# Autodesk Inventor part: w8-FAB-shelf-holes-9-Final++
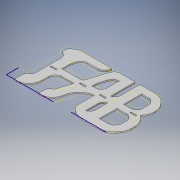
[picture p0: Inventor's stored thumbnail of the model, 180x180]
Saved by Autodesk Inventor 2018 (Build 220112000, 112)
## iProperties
Created: 2018-03
Part Number: w8-FAB-shelf-holes-9-Final++
Material: Generic
Document SubType Name: Modeling
Designer: katin
Density: 1 g/cm^3
Appearance: Default
Mass: 2764.59 g
Surface Area: 5789.53 cm^2
Volume: 2764.59 cm^3
Author: katin
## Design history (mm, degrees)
sketch "Sketch1"
  geometry: L1 (0, -103.188)-(-76.2, -103.188); L2 (-382.588, -407.987)-(-201.613, -407.987); L3 (-201.613, -407.987)-(-179.387, -330.2); L4 (-179.387, -330.2)-(-179.387, -303.315); L5 (-179.387, -303.315)-(-382.588, -303.315); L6 (-382.588, -303.315)-(-382.588, -330.2); L7 (-382.588, -330.2)-(-404.813, -407.987); L8 (-404.813, -407.987)-(-446.104, -500); L9 (-914.4, -410.18)-(-914.4, -330.2); L10 (-914.4, -330.2)-(-863.6, -279.4); L11 (-863.6, -279.4)-(-941.188, -201.812); L12 (-941.188, -100.013)-(-863.6, 0); L13 (-611.188, -500)-(-611.188, -274.637); L14 (-660.987, -274.638)-(-660.987, -501.799); L15 (-660.987, -203.2)-(-660.987, -104.775); L16 (-611.188, -104.775)-(-660.987, -104.775); L17 (-458.721, -302.879)-(-458.721, -330.2); L18 (-458.721, -330.2)-(-480.946, -407.987); L19 (-480.946, -407.987)-(-534.987, -407.987); L20 (-534.987, -407.987)-(-534.988, -302.879); L21 (-534.988, -302.879)-(-458.721, -302.879); L22 (-180.346, -201.117)-(-180.346, -104.775); L23 (-180.346, -104.775)-(-330, -104.775); L24 (-180.346, -201.117)-(-380.371, -201.117); L25 (-380.371, -201.117)-(-330, -104.775); L26 (-458.721, -201.117)-(-458.721, -104.775); L27 (-458.721, -201.117)-(-534.987, -201.117); L28 (-534.987, -201.117)-(-534.987, -104.775); L29 (-739.719, -407.987)-(-739.719, -306.388); L30 (-739.719, -407.987)-(-815.975, -407.987); L31 (-841.375, -354.012)-(-841.375, -381); L32 (-841.375, -381)-(-815.975, -407.987); L33 (-382.588, -407.987)-(-424.795, -502.08); L34 (-79.965, -502.08)-(-424.795, -502.08); L35 (-611.188, -104.775)-(-611.188, -203.2); L36 (-611.188, -500)-(-446.104, -500); L37 (0, -103.188)-(0, 0); L38 (-941.188, -201.812)-(-941.188, -100.013); L39 (0, -103.188)-(0, 0); L40 (0, 0)-(-406.4, 0); L41 (-406.4, 0)-(-458.721, -104.775); L42 (-534.987, -104.775)-(-558.8, 0); L43 (-611.188, -203.2)-(-660.987, -233.363); L44 (-660.987, -233.363)-(-660.987, -203.2); L45 (-558.8, 0)-(-863.6, 0); L46 (0, 0)-(-406.4, 0); L47 (-79.965, -502.08)-(-50.58, -485.849); L48 (-50.58, -485.849)-(-50.58, -407.987); L49 (-50.58, -407.987)-(-76.2, -407.987); L50 (-76.2, -407.987)-(-76.2, -103.188); L51 (-841.375, -354.012)-(-793.75, -306.388); L52 (-793.75, -306.388)-(-739.719, -306.388); L53 (-611.188, -274.637)-(-660.987, -274.638); L54 (-739.762, -201.612)-(-739.762, -103.187); L55 (-739.762, -103.187)-(-836.612, -103.188); L56 (-836.612, -103.188)-(-863.6, -138.112); L57 (-863.6, -138.112)-(-863.6, -176.213); L58 (-863.6, -176.213)-(-838.2, -201.612); L59 (-838.2, -201.612)-(-739.762, -201.612); L60 (-914.4, -410.18)-(-838.2, -501.799); L61 (-838.2, -501.799)-(-660.987, -501.799); L62 (0, 0)-(-406.4, 0); L63 (-558.8, 0)-(-863.6, 0)
  constraints: 126 end point, 13 perpendicular, 13 point on line, 10 vertical, 9 horizontal, 3 collinear, 1 parallel
sketch "Sketch2"
  geometry: L1 (0, 0)-(-940, 0); L2 (-940, 0)-(-940, -500); L3 (-940, -500)-(0, -500); L4 (0, -500)-(0, 0)
  constraints: 8 end point, 2 parallel, 1 horizontal, 1 perpendicular
  dimensions: "d10" = 940 distance of L3.end L2.end; "d11" = 500 distance of L2.end L1.end
extrude "Extrusion2" new body sketch "Sketch2" distance "d12" = 11; taper "d13" = 0 deg
sketch "Sketch3"
  geometry: L1 (0, 0)-(0, 500) reference; L2 (0, 408.758)-(113.674, 408.758); L3 (113.674, 408.758)-(113.674, 94.825); L4 (113.674, 94.825)-(0, 94.825); L5 (0, 94.825)-(0, 408.758); L6 (611.188, 500.062)-(650.182, 500.062); L7 (650.182, 500.062)-(650.182, 287.702); L8 (650.182, 287.702)-(611.188, 287.702); L9 (611.188, 287.702)-(611.188, 500.062); L10 (0, 500)-(129.919, 500); L11 (0, 500)-(940, 500) reference; L12 (129.919, 500)-(0, 408.758); L13 (0, 500)-(0, 408.758); L14 (739.775, 406.4)-(739.775, 307.975); L15 (739.775, 307.975)-(793.75, 307.975); L16 (793.75, 307.975)-(836.612, 350.838); L17 (836.612, 350.838)-(841.375, 355.6); L18 (841.375, 355.6)-(841.375, 381); L19 (841.375, 381)-(806.218, 418.355); L20 (806.218, 418.355)-(739.775, 418.355); L21 (739.775, 418.355)-(739.775, 406.4)
  constraints: 38 end point, 6 parallel, 4 perpendicular, 4 point on line, 2 horizontal, 1 collinear, 1 vertical
extrude "Extrusion3" cut sketch "Sketch3" distance "d14" = 150; taper "d15" = 0 deg
sketch "Sketch4"
  geometry: L1 (0, 500)-(940, 500) reference; L2 (839.788, 500)-(914.4, 411.163); L3 (914.4, 411.163)-(914.4, 310.193); L4 (914.4, 310.193)-(880.473, 275.82); L5 (880.473, 275.82)-(940, 217.064); L6 (940, 217.064)-(940, 500); L7 (940, 500)-(839.788, 500); L8 (940, 0)-(940, 500) reference; L9 (940, 99.14)-(940, 0); L10 (940, 0)-(863.6, 0); L11 (0, 0)-(940, 0) reference; L12 (940, 99.14)-(863.6, 0); L13 (728.744, 226.212)-(728.744, 72.721); L14 (728.744, 72.721)-(830.691, 72.721); L15 (830.691, 72.721)-(864.394, 116.456); L16 (864.394, 116.456)-(864.405, 192.017); L17 (864.405, 192.017)-(829.761, 226.212); L18 (829.761, 226.212)-(728.744, 226.212); L19 (649.575, 72.721)-(649.575, 226.081); L20 (649.575, 226.081)-(611.188, 202.869); L21 (611.188, 202.869)-(611.188, 72.721); L22 (611.188, 72.721)-(649.575, 72.721); L23 (727.378, 439.44)-(727.378, 283.141); L24 (727.378, 283.141)-(801.955, 283.141); L25 (801.955, 283.141)-(841.375, 322.561); L26 (841.375, 322.561)-(841.375, 403.65); L27 (841.375, 403.65)-(807.69, 439.44); L28 (807.69, 439.44)-(727.378, 439.44); L29 (534.987, 283.141)-(534.987, 439.44); L30 (534.987, 439.44)-(490.381, 439.44); L31 (490.381, 439.44)-(455.193, 321.307); L32 (455.193, 321.307)-(455.193, 283.141); L33 (455.193, 283.141)-(534.987, 283.141); L34 (534.987, 226.027)-(534.987, 72.721); L35 (534.987, 72.721)-(560.388, 0); L36 (560.388, 0)-(405.603, 0); L37 (455.193, 72.721)-(405.603, 0); L38 (455.193, 72.721)-(455.193, 226.027); L39 (455.193, 226.027)-(534.987, 226.027); L40 (250.031, 72.721)-(195.665, 72.721); L41 (195.665, 72.721)-(195.665, 226.027); L42 (195.665, 226.027)-(354.575, 226.027); L43 (354.575, 226.027)-(250.031, 72.721); L44 (195.665, 283.141)-(195.665, 362.436); L45 (195.665, 362.436)-(218.603, 439.44); L46 (218.603, 439.44)-(389.781, 439.44); L47 (389.781, 439.44)-(415.52, 500); L48 (415.52, 500)-(447.675, 500); L49 (611.188, 500)-(129.919, 500) reference; L50 (195.665, 283.141)-(380.412, 283.141); L51 (380.412, 283.141)-(380.412, 300.037); L52 (380.412, 300.037)-(421.936, 439.44); L53 (421.936, 439.44)-(447.675, 500); L54 (415.52, 500)-(447.675, 500); 1 further point
  constraints: 100 end point, 28 point on line, 12 perpendicular, 11 parallel, 3 vertical, 2 collinear
extrude "Extrusion4" cut sketch "Sketch4" distance "d16" = 150; taper "d17" = 0 deg
fillet "Fillet1" dims "d18" = 50
fillet "Fillet2" dims "d19" = 50
fillet "Fillet3" dims "d20" = 50
fillet "Fillet4" dims "d21" = 60
fillet "Fillet7" dims "d24" = 30
fillet "Fillet8" dims "d25" = 50
fillet "Fillet9" dims "d26" = 50
fillet "Fillet10" dims "d27" = 50
fillet "Fillet13" dims "d30" = 40
fillet "Fillet14" dims "d31" = 120
fillet "Fillet15" dims "d32" = 120
fillet "Fillet16" dims "d33" = 120
fillet "Fillet17" dims "d34" = 50
fillet "Fillet18" dims "d35" = 50
fillet "Fillet19" dims "d36" = 170
fillet "Fillet20" dims "d37" = 65
fillet "Fillet21" dims "d38" = 50
fillet "Fillet22" dims "d39" = 5
fillet "Fillet25" dims "d42" = 25
fillet "Fillet26" dims "d43" = 50
fillet "Fillet27" dims "d44" = 90
sketch "Sketch5"
  geometry: L1 (195.665, 72.721)-(195.665, 0); L2 (195.665, 0)-(278.632, 0); L3 (0, 0)-(285.193, 0) reference; L4 (278.632, 80.606)-(278.632, 0); L5 (278.632, 80.606)-(278.632, 104.775); L6 (223.608, 72.721)-(195.665, 72.721) reference; L7 (278.632, 104.775)-(195.665, 72.721)
  constraints: 10 end point, 2 vertical, 1 perpendicular, 1 point on line
extrude "Extrusion5" cut sketch "Sketch5" distance "d45" = 150; taper "d46" = 0 deg
sketch "Sketch6"
  geometry: L1 (463.037, 222.547)-(398.463, 127.297); L2 (398.463, 127.297)-(398.463, 22.263); L3 (455.193, 283.141)-(455.193, 311.832) reference; L4 (398.463, 22.263)-(534.988, 22.263); L5 (534.987, 226.027)-(534.987, 72.721) reference; L6 (534.988, 22.263)-(534.987, 226.027); L7 (534.987, 226.027)-(463.037, 222.547); 2 further points
  constraints: 10 end point, 2 perpendicular, 1 parallel
extrude "Extrusion6" cut sketch "Sketch6" distance "d48" = 150; taper "d49" = 0 deg
fillet "Fillet29" dims "d50" = 100
fillet "Fillet30" dims "d51" = 40
sketch "Sketch7"
  geometry: L1 (242.804, 83.41)-(242.804, 226.022); L2 (242.804, 226.022)-(357.713, 226.022); L3 (306.387, 83.41)-(242.804, 83.41); L4 (357.713, 226.022)-(313.861, 83.41); L5 (313.861, 83.41)-(242.804, 83.41); 1 further point
  constraints: 10 end point, 1 horizontal, 1 parallel, 1 perpendicular, 1 vertical
extrude "Extrusion7" cut sketch "Sketch7" distance "d52" = 150; taper "d53" = 0 deg
fillet "Fillet31" dims "d54" = 40
sketch "Sketch8"
  geometry: L1 (505.193, 226.027)-(534.987, 226.027) reference; L2 (534.987, 226.027)-(534.987, 72.721) reference; L3 (534.987, 127.541)-(534.987, 226.027); L4 (403.342, 127.541)-(534.987, 127.541); L5 (534.987, 226.027)-(435.488, 226.027); L6 (435.488, 226.027)-(403.342, 127.541); A1 r 100 centre (498.406, 96.512) between (415.634, 152.627) and (398.434, 98.891) reference; A2 r 100 centre (498.406, 96.512) between (415.634, 152.627) and (398.434, 98.891) reference; 2 further points
  constraints: 8 end point, 2 horizontal, 1 point on circle, 1 point on line, 1 tangent, 1 vertical
extrude "Extrusion8" cut sketch "Sketch8" distance "d55" = 150; taper "d56" = 0 deg
fillet "Fillet32" dims "d57" = 160
sketch "Sketch9"
  geometry: L1 (841.375, 322.561)-(801.955, 283.141) reference; L2 (841.375, 322.561)-(841.375, 298.749); L3 (841.375, 298.749)-(842.323, 283.141); L4 (842.323, 283.141)-(801.955, 283.141); 1 further point
  constraints: 6 end point, 1 perpendicular, 1 vertical
extrude "Extrusion9" cut sketch "Sketch9" distance "d58" = 150; taper "d59" = 0 deg
fillet "Fillet33" dims "d60" = 50
fillet "Fillet34" dims "d61" = 110
fillet "Fillet43" dims "d70" = 50
fillet "Fillet44" dims "d71" = 5
fillet "Fillet45" dims "d72" = 40
sketch "Sketch10"
  geometry: L1 (-1.587, 508)-(69.85, 508); L2 (69.85, 508)-(69.85, -22.225); L3 (69.85, -22.225)-(-1.587, -22.225); L4 (-1.587, -22.225)-(-1.587, 508); 1 further point
  constraints: 8 end point, 2 parallel, 1 horizontal, 1 perpendicular
extrude "Extrusion10" cut sketch "Sketch10" distance "d73" = 150; taper "d74" = 0 deg
fillet "Fillet46" dims "d75" = 40
fillet "Fillet47" dims "d76" = 5
fillet "Fillet48" dims "d77" = 5
fillet "Fillet49" dims "d78" = 5
sketch "Sketch12"
  geometry: C1 r 5 at (151.971, -436.562); C2 r 5 at (858.837, -436.562); 1 further point
  constraints: 2 centre point
  dimensions: "d85" = 10 diameter of C1; "d86" = 10 diameter of C2
extrude "Extrusion11" cut sketch "Sketch12" distance "d89" = 6; taper "d90" = 0 deg
sketch "Sketch16"
  geometry: L1 (131.762, 258.023)-(181.762, 258.023); L2 (181.762, 258.023)-(181.762, 247.023); L3 (181.762, 247.023)-(131.762, 247.023); L4 (131.762, 247.023)-(131.762, 258.023); L5 (382.587, 258.023)-(432.587, 258.023); L6 (432.587, 258.023)-(432.587, 247.023); L7 (432.587, 247.023)-(382.587, 247.023); L8 (382.587, 247.023)-(382.587, 258.023); L9 (554.038, 258.023)-(604.038, 258.023); L10 (604.038, 258.023)-(604.038, 247.023); L11 (604.038, 247.023)-(554.038, 247.023); L12 (554.038, 247.023)-(554.038, 258.023); L13 (817.562, 258.023)-(867.562, 258.023); L14 (867.562, 258.023)-(867.562, 247.023); L15 (867.562, 247.023)-(817.562, 247.023); L16 (817.562, 247.023)-(817.562, 258.023); 1 further point
  constraints: 32 end point, 8 parallel, 4 horizontal, 4 perpendicular, 2 point on line
  dimensions: "d106" = 50 distance of L2.end L3.end; "d107" = 11 distance of L1.end L2.end; "d108" = 50 distance of L6.end L7.end; "d109" = 11 distance of L5.end L6.end; "d110" = 50 distance of L10.end L11.end; "d111" = 11 distance of L9.end L10.end; "d112" = 50 distance of L14.end L15.end; "d113" = 11 distance of L13.end L14.end
extrude "Extrusion15" cut sketch "Sketch16" distance "d114" = 110; taper "d115" = 0 deg
sketch "Sketch22"
  geometry: L1 (152.028, -447.675)-(152.028, -423.863); L2 (156.328, -447.675)-(156.328, -423.863); L3 (147.728, -423.863)-(147.728, -447.675); L4 (858.824, -447.687)-(858.824, -423.875); L5 (863.124, -447.687)-(863.124, -423.875); L6 (854.524, -423.875)-(854.524, -447.687); A1 r 4.3 centre (152.028, -447.675) between (147.728, -447.675) and (156.328, -447.675); A2 r 4.3 centre (152.028, -423.863) between (156.328, -423.863) and (147.728, -423.863); A3 r 4.3 centre (858.824, -447.687) between (854.524, -447.687) and (863.124, -447.687); A4 r 4.3 centre (858.824, -423.875) between (863.124, -423.875) and (854.524, -423.875); 3 further points
  constraints: 16 end point, 8 point on circle, 8 tangent, 4 centre point, 2 midpoint, 2 parallel, 2 vertical
  dimensions: "d143" = 8.6 diameter of A2; "d150" = 32.4125 dimension on A2 A1; "d151" = 8.6 diameter of A4; "d152" = 32.4125 dimension on A4 A3; "d153" = 8.6 distance between parallel lines of L6 L5 (derived); "d154" = 4.3 radius of A3 (derived); "d155" = 11.90625 distance of point (858.824, -435.781) L4.start (derived)
extrude "Extrusion20" cut sketch "Sketch22" distance "d144" = 6; taper "d145" = 0 deg
sketch "Sketch24"
  geometry: L1 (858.844, -447.663)-(858.844, -423.85); L2 (863.144, -447.663)-(863.144, -423.85); L3 (854.544, -423.85)-(854.544, -447.663); A1 r 4.3 centre (858.844, -447.663) between (854.544, -447.663) and (863.144, -447.663); A2 r 4.3 centre (858.844, -423.85) between (863.144, -423.85) and (854.544, -423.85); 2 further points
  constraints: 8 end point, 4 point on circle, 4 tangent, 2 centre point, 1 midpoint, 1 parallel, 1 vertical
  dimensions: "d156" = 8.6 diameter of A2; "d157" = 32.413 dimension on A2 A1
extrude "Extrusion22" cut sketch "Sketch24" distance "d158" = 6; taper "d159" = 0 deg
body "Solid2"
